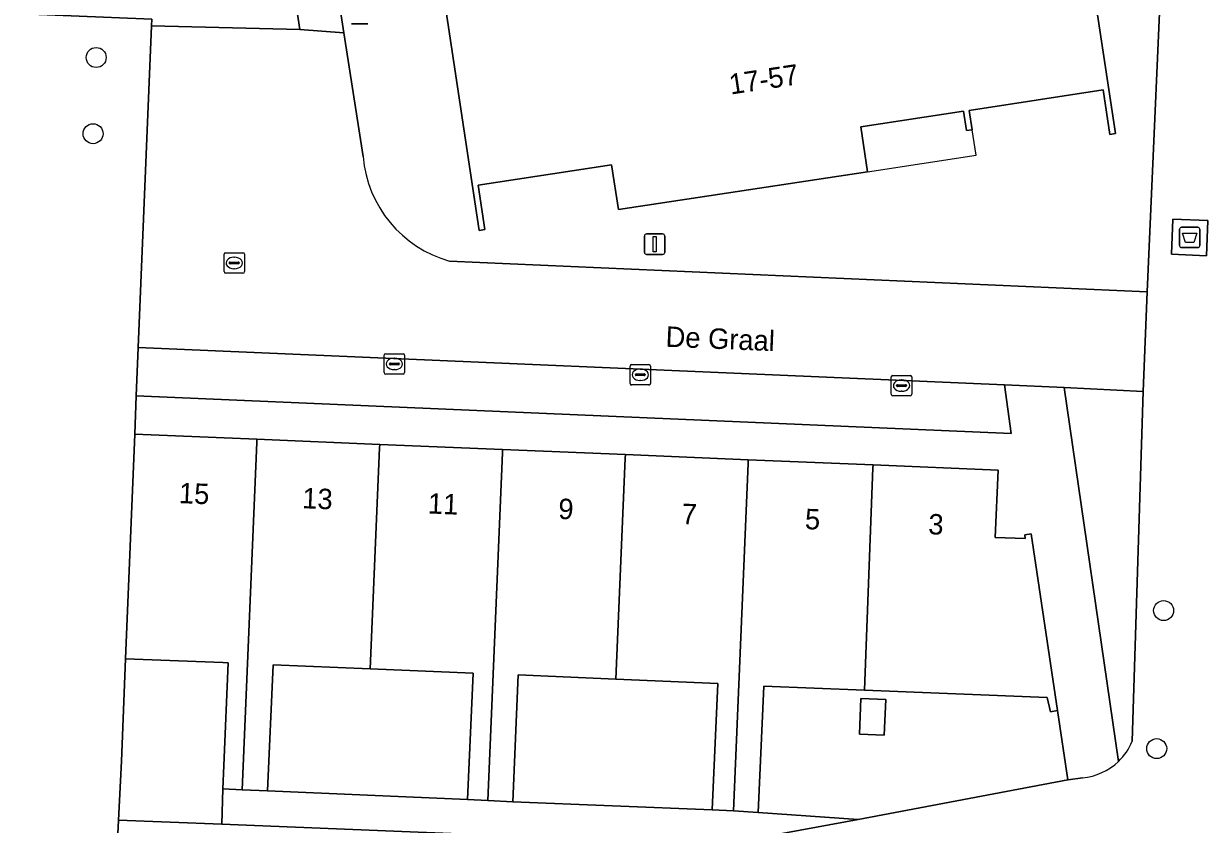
# Model space of a CAD drawing. Extents: x 160077 to 160948, y 386481 to 387498.
# Drawn here: x 160670.3 to 160728.2, y 386806 to 386845.2 of the extents above; entities that cross this region are included whole.
import ezdxf

# ---------------------------------------------------------------- set-up
doc = ezdxf.new("R2010")
doc.units = 0
for name, color, linetype in [('IMGEO_Afval_apart_plaats', 7, 'Continuous'), ('IMGEO_Boom', 7, 'Continuous'), ('IMGEO_Erf', 7, 'Continuous'), ('IMGEO_Groenvoorziening', 7, 'Continuous'), ('IMGEO_Hek', 7, 'Continuous'), ('IMGEO_Kolk', 7, 'Continuous'), ('IMGEO_Lichtmast', 7, 'Continuous'), ('IMGEO_Openbare_ruimte_label', 7, 'Continuous'), ('IMGEO_Pand', 7, 'Continuous'), ('IMGEO_Pand_nummerreeks', 7, 'Continuous'), ('IMGEO_Pand_overbouw', 7, 'Continuous'), ('IMGEO_Parkeervlak_open', 7, 'Continuous'), ('IMGEO_Rijbaan_lokaal_open', 7, 'Continuous'), ('IMGEO_Voetpad_gesloten', 7, 'Continuous'), ('IMGEO_Voetpad_open', 7, 'Continuous')]:
    doc.layers.add(name, color=color, linetype=linetype)

msp = doc.modelspace()

# ---------------------------------------------------------------- linework, layer by layer
at = {"layer": 'IMGEO_Afval_apart_plaats'}
for p, q in [((160726.919, 386834.297), (160726.919, 386835.097)), ((160726.919, 386835.097), (160726.919, 386834.297)), ((160727.019, 386835.197), (160727.809, 386835.197)), ((160727.809, 386835.197), (160727.019, 386835.197)), ((160727.909, 386835.097), (160727.909, 386834.297)), ((160727.909, 386834.297), (160727.909, 386835.097)), ((160727.809, 386834.197), (160727.019, 386834.197)), ((160727.019, 386834.197), (160727.809, 386834.197))]:
    msp.add_line(p, q, dxfattribs=at)
msp.add_lwpolyline([(160727.062, 386834.911), (160727.766, 386834.911), (160727.617, 386834.441), (160727.211, 386834.441), (160727.062, 386834.911)], dxfattribs=at)
for centre, start, end in [((160727.019, 386835.097), 90, 180), ((160727.019, 386835.097), 90, 180), ((160727.809, 386835.097), 0, 90), ((160727.809, 386835.097), 360, 90), ((160727.019, 386834.297), 180, 270), ((160727.019, 386834.297), 180, 270), ((160727.809, 386834.297), 270, 0), ((160727.809, 386834.297), 270, 0)]:
    msp.add_arc(centre, 0.1, start, end, dxfattribs=at)
at = {"layer": 'IMGEO_Boom'}
for centre in [(160673.83, 386843.508), (160673.676, 386839.775), (160726.139, 386816.428), (160725.8, 386809.667)]:
    msp.add_circle(centre, 0.489, dxfattribs=at)
at = {"layer": 'IMGEO_Erf'}
for points in [[(160681.407, 386874.372), (160685.964, 386844.721), (160686.909, 386838.653)], [(160691.151, 386833.539), (160725.339, 386832.034), (160727.013, 386870.072)]]:
    msp.add_lwpolyline(points, dxfattribs=at)
for points in [[(160674.502, 386797.454), (160674.929, 386806.169), (160675.07, 386809.047), (160675.272, 386814.07), (160675.716, 386825.063), (160675.794, 386826.947), (160675.891, 386829.313), (160676.542, 386845.055), (160676.555, 386845.381), (160668.235, 386845.73), (160669.487, 386869.91), (160666.813, 386871.238), (160603.434, 386849.369), (160600.755, 386785.404), (160608.542, 386785.099), (160611.61, 386785.659), (160625.143, 386788.129), (160667.256, 386796.073)], [(160719.039, 386870.969), (160719.083, 386870.688), (160716.909, 386870.357), (160717.908, 386863.813), (160720.082, 386864.138), (160723.782, 386839.784), (160723.51, 386839.743), (160723.179, 386841.918), (160716.615, 386840.919), (160716.76, 386839.97), (160716.483, 386839.928), (160716.338, 386840.877), (160711.296, 386840.109), (160711.631, 386837.915), (160699.418, 386836.068), (160699.087, 386838.251), (160692.542, 386837.255), (160692.873, 386835.08), (160692.596, 386835.037), (160688.915, 386859.399), (160691.091, 386859.728), (160690.101, 386866.274), (160687.925, 386865.945), (160687.883, 386866.221)], [(160680.29, 386813.868), (160680.029, 386813.879), (160675.272, 386814.07), (160675.07, 386809.047), (160674.929, 386806.169), (160679.98, 386805.966), (160680.037, 386807.699), (160680.088, 386808.845)], [(160682.507, 386813.779), (160682.232, 386807.601), (160692.02, 386807.182), (160692.295, 386813.36), (160687.263, 386813.575)], [(160694.511, 386813.28), (160694.244, 386807.065), (160704.021, 386806.674), (160704.296, 386812.852), (160699.3, 386813.071)], [(160720.935, 386811.538), (160720.595, 386811.471), (160720.429, 386812.177), (160711.474, 386812.53), (160706.55, 386812.724), (160706.275, 386806.546), (160711.175, 386806.204), (160721.441, 386808.138)], [(160712.518, 386812.07), (160712.449, 386810.322), (160711.234, 386810.37), (160711.302, 386812.118)]]:
    msp.add_lwpolyline(points, close=True, dxfattribs=at)
msp.add_arc((160692.706, 386839.145), 5.818, 184.85234, 254.49824, dxfattribs=at)
at = {"layer": 'IMGEO_Groenvoorziening'}
for points in [[(160676.694, 386874.549), (160668.825, 386871.932), (160666.813, 386871.238), (160669.487, 386869.91), (160668.235, 386845.73), (160676.555, 386845.381), (160676.542, 386845.055), (160683.812, 386844.878), (160679.252, 386874.896)], [(160724.597, 386810.026), (160725.137, 386827.154), (160721.259, 386827.344), (160723.927, 386809.045)]]:
    msp.add_lwpolyline(points, dxfattribs=at)
msp.add_lwpolyline([(160702.849, 386805.045), (160679.98, 386805.966), (160674.929, 386806.169), (160674.502, 386797.454), (160674.9, 386797.53), (160674.597, 386799.312), (160702.825, 386804.662)], close=True, dxfattribs=at)
msp.add_arc((160721.922, 386811.134), 2.896, 313.8315, 337.50418, dxfattribs=at)
at = {"layer": 'IMGEO_Hek'}
for points in [[(160676.542, 386845.055), (160676.555, 386845.381), (160668.235, 386845.73), (160669.487, 386869.91), (160666.813, 386871.238)], [(160675.891, 386829.313), (160676.542, 386845.055)], [(160675.794, 386826.947), (160675.891, 386829.313)], [(160675.716, 386825.063), (160675.794, 386826.947)], [(160674.502, 386797.454), (160675.07, 386809.047)]]:
    msp.add_lwpolyline(points, dxfattribs=at)
at = {"layer": 'IMGEO_Kolk'}
for p, q in [((160680.169, 386833.947), (160681.021, 386833.947)), ((160680.094, 386833.021), (160680.094, 386833.873)), ((160680.353, 386833.441), (160680.353, 386833.453)), ((160680.791, 386833.404), (160680.393, 386833.404)), ((160680.396, 386833.49), (160680.794, 386833.49)), ((160680.582, 386833.727), (160680.607, 386833.727)), ((160680.837, 386833.453), (160680.837, 386833.441)), ((160681.095, 386833.873), (160681.095, 386833.021)), ((160681.021, 386832.947), (160680.169, 386832.947)), ((160680.605, 386833.167), (160680.58, 386833.167)), ((160687.942, 386828.077), (160687.942, 386828.929)), ((160688.017, 386829.003), (160688.869, 386829.003)), ((160688.43, 386828.783), (160688.455, 386828.783)), ((160688.943, 386828.929), (160688.943, 386828.077)), ((160688.201, 386828.497), (160688.201, 386828.509)), ((160688.639, 386828.46), (160688.241, 386828.46)), ((160688.244, 386828.546), (160688.642, 386828.546)), ((160688.453, 386828.223), (160688.428, 386828.223)), ((160688.685, 386828.509), (160688.685, 386828.497)), ((160699.991, 386827.546), (160699.991, 386828.398)), ((160700.066, 386828.472), (160700.918, 386828.472)), ((160700.479, 386828.252), (160700.504, 386828.252)), ((160700.992, 386828.398), (160700.992, 386827.546)), ((160688.869, 386828.003), (160688.017, 386828.003)), ((160700.25, 386827.966), (160700.25, 386827.978)), ((160700.688, 386827.929), (160700.29, 386827.929)), ((160700.293, 386828.015), (160700.691, 386828.015)), ((160700.502, 386827.692), (160700.477, 386827.692)), ((160700.734, 386827.978), (160700.734, 386827.966)), ((160712.794, 386827.017), (160712.794, 386827.869)), ((160712.869, 386827.943), (160713.721, 386827.943)), ((160713.282, 386827.723), (160713.307, 386827.723)), ((160713.795, 386827.869), (160713.795, 386827.017)), ((160700.918, 386827.472), (160700.066, 386827.472)), ((160713.053, 386827.437), (160713.053, 386827.449)), ((160713.491, 386827.4), (160713.093, 386827.4)), ((160713.096, 386827.486), (160713.494, 386827.486)), ((160713.305, 386827.163), (160713.28, 386827.163)), ((160713.537, 386827.449), (160713.537, 386827.437)), ((160713.721, 386826.943), (160712.869, 386826.943))]:
    msp.add_line(p, q, dxfattribs=at)
for points in [[(160680.169, 386833.947), (160681.021, 386833.947)], [(160680.094, 386833.021), (160680.094, 386833.873)], [(160681.095, 386833.873), (160681.095, 386833.021)], [(160681.021, 386832.947), (160680.169, 386832.947)], [(160687.942, 386828.077), (160687.942, 386828.929)], [(160688.017, 386829.003), (160688.869, 386829.003)], [(160688.943, 386828.929), (160688.943, 386828.077)], [(160699.991, 386827.546), (160699.991, 386828.398)], [(160700.066, 386828.472), (160700.918, 386828.472)], [(160700.992, 386828.398), (160700.992, 386827.546)], [(160688.869, 386828.003), (160688.017, 386828.003)], [(160712.794, 386827.017), (160712.794, 386827.869)], [(160712.869, 386827.943), (160713.721, 386827.943)], [(160713.795, 386827.869), (160713.795, 386827.017)], [(160700.918, 386827.472), (160700.066, 386827.472)], [(160713.721, 386826.943), (160712.869, 386826.943)]]:
    msp.add_lwpolyline(points, dxfattribs=at)
for centre, radius, start, end in [((160680.171, 386833.871), 0.0765, 91.55205, 178.44795), ((160680.171, 386833.871), 0.0765, 91.55205, 178.44795), ((160681.019, 386833.871), 0.0765, 1.55205, 88.44795), ((160681.019, 386833.871), 0.0765, 1.55205, 88.44795), ((160680.393, 386833.45), 0.0403, 85.87752, 175.75265), ((160680.39, 386833.44), 0.0366, 178.93798, 274.71019), ((160680.794, 386833.447), 0.043, 264.86636, 352.45326), ((160680.798, 386833.452), 0.0386, 1.73085, 96.63898), ((160680.171, 386833.023), 0.0765, 181.55205, 268.44795), ((160680.171, 386833.023), 0.0765, 181.55205, 268.44795), ((160681.019, 386833.023), 0.0765, 271.55205, 358.44795), ((160681.019, 386833.023), 0.0765, 271.55205, 358.44795), ((160688.019, 386828.927), 0.0765, 91.55205, 178.44795), ((160688.019, 386828.927), 0.0765, 91.55205, 178.44795), ((160688.867, 386828.927), 0.0765, 1.55205, 88.44795), ((160688.867, 386828.927), 0.0765, 1.55205, 88.44795), ((160688.241, 386828.506), 0.0403, 85.87752, 175.75265), ((160688.238, 386828.496), 0.0366, 178.93798, 274.71019), ((160688.642, 386828.503), 0.043, 264.86636, 352.45326), ((160688.646, 386828.508), 0.0386, 1.73085, 96.63898), ((160700.068, 386828.396), 0.0765, 91.55205, 178.44795), ((160700.068, 386828.396), 0.0765, 91.55205, 178.44795), ((160700.916, 386828.396), 0.0765, 1.55205, 88.44795), ((160700.916, 386828.396), 0.0765, 1.55205, 88.44795), ((160688.019, 386828.079), 0.0765, 181.55205, 268.44795), ((160688.019, 386828.079), 0.0765, 181.55205, 268.44795), ((160688.867, 386828.079), 0.0765, 271.55205, 358.44795), ((160688.867, 386828.079), 0.0765, 271.55205, 358.44795), ((160700.29, 386827.975), 0.0403, 85.87752, 175.75265), ((160700.287, 386827.965), 0.0366, 178.93798, 274.71019), ((160700.691, 386827.972), 0.043, 264.86636, 352.45326), ((160700.695, 386827.977), 0.0386, 1.73085, 96.63898), ((160712.871, 386827.867), 0.0765, 91.55205, 178.44795), ((160712.871, 386827.867), 0.0765, 91.55205, 178.44795), ((160713.719, 386827.867), 0.0765, 1.55205, 88.44795), ((160713.719, 386827.867), 0.0765, 1.55205, 88.44795), ((160700.068, 386827.548), 0.0765, 181.55205, 268.44795), ((160700.068, 386827.548), 0.0765, 181.55205, 268.44795), ((160700.916, 386827.548), 0.0765, 271.55205, 358.44795), ((160700.916, 386827.548), 0.0765, 271.55205, 358.44795), ((160712.871, 386827.019), 0.0765, 181.55205, 268.44795), ((160712.871, 386827.019), 0.0765, 181.55205, 268.44795), ((160713.093, 386827.446), 0.0403, 85.87752, 175.75265), ((160713.09, 386827.436), 0.0366, 178.93798, 274.71019), ((160713.494, 386827.443), 0.043, 264.86636, 352.45326), ((160713.498, 386827.448), 0.0386, 1.73085, 96.63898), ((160713.719, 386827.019), 0.0765, 271.55205, 358.44795), ((160713.719, 386827.019), 0.0765, 271.55205, 358.44795)]:
    msp.add_arc(centre, radius, start, end, dxfattribs=at)
for centre, major_axis, ratio, start_param, end_param in [((160680.581, 386833.447), (-0.387, 0.002), 0.722429, 4.712389, 7.853982), ((160680.606, 386833.447), (-0.39, 0.002), 0.717154, 1.570796, 4.712389), ((160688.429, 386828.503), (-0.387, 0.002), 0.722429, 4.712389, 7.853982), ((160688.454, 386828.503), (-0.39, 0.002), 0.717154, 1.570796, 4.712389), ((160700.478, 386827.972), (-0.387, 0.002), 0.722429, 4.712389, 7.853982), ((160700.503, 386827.972), (-0.39, 0.002), 0.717154, 1.570796, 4.712389), ((160713.281, 386827.443), (-0.387, 0.002), 0.722429, 4.712389, 7.853982), ((160713.306, 386827.443), (-0.39, 0.002), 0.717154, 1.570796, 4.712389)]:
    msp.add_ellipse(centre, major_axis=major_axis, ratio=ratio, start_param=start_param, end_param=end_param, dxfattribs=at)
at = {"layer": 'IMGEO_Lichtmast'}
for p, q in [((160687.137, 386845.162), (160686.347, 386845.162)), ((160686.347, 386845.162), (160687.137, 386845.162)), ((160700.698, 386833.965), (160700.698, 386834.765)), ((160700.698, 386834.765), (160700.698, 386833.965)), ((160700.798, 386834.865), (160701.588, 386834.865)), ((160701.588, 386834.865), (160700.798, 386834.865)), ((160701.688, 386834.765), (160701.688, 386833.965)), ((160701.688, 386833.965), (160701.688, 386834.765)), ((160701.588, 386833.865), (160700.798, 386833.865)), ((160700.798, 386833.865), (160701.588, 386833.865))]:
    msp.add_line(p, q, dxfattribs=at)
msp.add_lwpolyline([(160701.118, 386834.74), (160701.268, 386834.74), (160701.268, 386833.99), (160701.118, 386833.99), (160701.118, 386834.74)], dxfattribs=at)
for centre, start, end in [((160700.798, 386834.765), 90, 180), ((160700.798, 386834.765), 90, 180), ((160701.588, 386834.765), 0, 90), ((160701.588, 386834.765), 360, 90), ((160700.798, 386833.965), 180, 270), ((160700.798, 386833.965), 180, 270), ((160701.588, 386833.965), 270, 0), ((160701.588, 386833.965), 270, 0)]:
    msp.add_arc(centre, 0.1, start, end, dxfattribs=at)
at = {"layer": 'IMGEO_Pand'}
for points in [[(160723.782, 386839.784), (160720.082, 386864.138), (160717.908, 386863.813), (160716.909, 386870.357), (160719.083, 386870.688), (160719.039, 386870.969), (160687.883, 386866.221), (160687.925, 386865.945), (160690.101, 386866.274), (160691.091, 386859.728), (160688.915, 386859.399), (160692.596, 386835.037), (160692.873, 386835.08), (160692.542, 386837.255), (160699.087, 386838.251), (160699.418, 386836.068), (160711.631, 386837.915), (160711.296, 386840.109), (160716.338, 386840.877), (160716.483, 386839.928), (160716.76, 386839.97), (160716.615, 386840.919), (160723.179, 386841.918), (160723.51, 386839.743)], [(160681.702, 386824.653), (160681.709, 386824.814), (160675.716, 386825.063), (160675.272, 386814.07), (160680.029, 386813.879), (160680.29, 386813.868), (160680.088, 386808.845), (160680.037, 386807.699), (160680.984, 386807.657)], [(160687.263, 386813.575), (160687.72, 386824.399), (160687.727, 386824.564), (160681.709, 386824.814), (160681.702, 386824.653), (160680.984, 386807.657), (160682.232, 386807.601), (160682.507, 386813.779)], [(160693.019, 386807.129), (160693.738, 386824.145), (160693.745, 386824.315), (160687.727, 386824.564), (160687.72, 386824.399), (160687.263, 386813.575), (160692.295, 386813.36), (160692.02, 386807.182)], [(160699.3, 386813.071), (160699.757, 386823.89), (160699.764, 386824.065), (160693.745, 386824.315), (160693.738, 386824.145), (160693.019, 386807.129), (160694.244, 386807.065), (160694.511, 386813.28)], [(160705.056, 386806.615), (160705.775, 386823.636), (160705.783, 386823.815), (160699.764, 386824.065), (160699.757, 386823.89), (160699.3, 386813.071), (160704.296, 386812.852), (160704.021, 386806.674)], [(160711.474, 386812.53), (160711.893, 386823.418), (160711.899, 386823.561), (160705.783, 386823.815), (160705.775, 386823.636), (160705.056, 386806.615), (160706.275, 386806.546), (160706.55, 386812.724)], [(160711.899, 386823.561), (160711.893, 386823.418), (160711.474, 386812.53), (160720.429, 386812.177), (160720.595, 386811.471), (160720.935, 386811.538), (160719.649, 386820.177), (160719.336, 386820.131), (160719.358, 386819.951), (160717.889, 386820.01), (160718.023, 386823.307)], [(160712.518, 386812.07), (160711.302, 386812.118), (160711.234, 386810.37), (160712.449, 386810.322)]]:
    msp.add_lwpolyline(points, close=True, dxfattribs=at)
at = {"layer": 'IMGEO_Pand_overbouw'}
msp.add_lwpolyline([(160716.76, 386839.97), (160716.483, 386839.928), (160716.338, 386840.877), (160711.296, 386840.109), (160711.631, 386837.915), (160716.951, 386838.72)], close=True, dxfattribs=at)
at = {"layer": 'IMGEO_Parkeervlak_open'}
msp.add_lwpolyline([(160675.794, 386826.947), (160718.66, 386825.104), (160718.337, 386827.488), (160675.891, 386829.313)], close=True, dxfattribs=at)
at = {"layer": 'IMGEO_Rijbaan_lokaal_open'}
msp.add_lwpolyline([(160686.909, 386838.653), (160685.964, 386844.721), (160683.812, 386844.878), (160676.542, 386845.055), (160675.891, 386829.313), (160718.337, 386827.488), (160721.259, 386827.344), (160725.137, 386827.154), (160725.339, 386832.034), (160691.151, 386833.539)], dxfattribs=at)
msp.add_arc((160692.706, 386839.145), 5.818, 184.85234, 254.49824, dxfattribs=at)
at = {"layer": 'IMGEO_Voetpad_gesloten'}
msp.add_lwpolyline([(160728.309, 386835.522), (160726.589, 386835.592), (160726.519, 386833.873), (160728.239, 386833.803)], close=True, dxfattribs=at)
at = {"layer": 'IMGEO_Voetpad_open'}
for points in [[(160679.252, 386874.896), (160683.812, 386844.878), (160685.964, 386844.721), (160681.407, 386874.372)], [(160728.309, 386835.522), (160728.239, 386833.803), (160726.519, 386833.873), (160726.589, 386835.592)], [(160680.037, 386807.699), (160679.98, 386805.966), (160702.849, 386805.045), (160702.825, 386804.662), (160704.872, 386805.04), (160711.175, 386806.204), (160706.275, 386806.546), (160705.056, 386806.615), (160704.021, 386806.674), (160694.244, 386807.065), (160693.019, 386807.129), (160692.02, 386807.182), (160682.232, 386807.601), (160680.984, 386807.657)]]:
    msp.add_lwpolyline(points, close=True, dxfattribs=at)
for points in [[(160727.013, 386870.072), (160725.339, 386832.034), (160725.137, 386827.154), (160724.597, 386810.026)], [(160723.927, 386809.045), (160721.259, 386827.344), (160718.337, 386827.488), (160718.66, 386825.104), (160675.794, 386826.947), (160675.716, 386825.063), (160681.709, 386824.814), (160687.727, 386824.564), (160693.745, 386824.315), (160699.764, 386824.065), (160705.783, 386823.815), (160711.899, 386823.561), (160718.023, 386823.307), (160717.889, 386820.01), (160719.358, 386819.951), (160719.336, 386820.131), (160719.649, 386820.177), (160720.935, 386811.538), (160721.441, 386808.138), (160721.453, 386808.14), (160722.155, 386808.242)], [(160722.155, 386808.242), (160721.453, 386808.14), (160721.441, 386808.138), (160711.175, 386806.204), (160704.872, 386805.04), (160702.825, 386804.662), (160674.597, 386799.312), (160674.9, 386797.53), (160674.502, 386797.454), (160667.256, 386796.073), (160625.143, 386788.129), (160611.61, 386785.659), (160611.261, 386774.569), (160611.199, 386773.064), (160614.688, 386772.962)]]:
    msp.add_lwpolyline(points, dxfattribs=at)
for centre, radius, start, end in [((160721.922, 386811.134), 2.896, 313.8315, 337.50418), ((160721.909, 386811.142), 2.91, 274.85087, 313.90542), ((160721.909, 386811.142), 2.91, 274.85087, 313.90542)]:
    msp.add_arc(centre, radius, start, end, dxfattribs=at)

# ---------------------------------------------------------------- texts
at = {"layer": 'IMGEO_Openbare_ruimte_label'}
msp.add_text('De Graal', height=1, rotation=357.64984, dxfattribs=at).set_placement((160701.718, 386829.347))
at = {"layer": 'IMGEO_Pand_nummerreeks'}
for s, rotation, p in [('17-57', 8.65408, (160704.925, 386841.689)), ('15', 357.62223, (160677.868, 386821.691)), ('13', 357.62324, (160683.912, 386821.44)), ('11', 357.62324, (160690.069, 386821.184)), ('9', 357.62324, (160696.459, 386820.919)), ('7', 357.62324, (160702.503, 386820.669)), ('5', 357.62324, (160708.547, 386820.418)), ('3', 357.62324, (160714.591, 386820.167))]:
    msp.add_text(s, height=1, rotation=rotation, dxfattribs=at).set_placement(p)

doc.saveas('drawing.dxf')
